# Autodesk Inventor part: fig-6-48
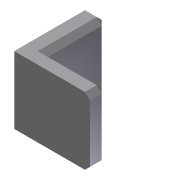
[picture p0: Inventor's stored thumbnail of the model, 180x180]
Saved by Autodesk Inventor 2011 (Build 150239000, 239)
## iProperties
Created: 2009-09
Part Number: fig-6-48
Document SubType Name: Modeling
Designer: Sham
Density: 1 g/cm^3
Author: Sham
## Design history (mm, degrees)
sketch "Sketch1"
  geometry: L1 (1.789, 30)-(1.789, -5); L2 (1.789, -5)-(36.789, -5); L3 (36.789, -5)-(36.789, -15); L4 (36.789, -15)-(-8.211, -15); L5 (-8.211, -15)-(-8.211, 30); L6 (-8.211, 30)-(1.789, 30)
  constraints: 12 end point, 6 perpendicular
  dimensions: "d0" = 10 distance of L5.end L1.start; "d1" = 35 distance of L1.start L1.end; "d2" = 45 distance of L3.end L4.end; "d3" = 10 distance of L2.end L3.end (derived)
extrude "Extrusion1" new body sketch "Sketch1" distance "d4" = 40; taper "d5" = 0 deg
chamfer "Chamfer1" distance "d6" = 3; stored, may be unused: second distance "d7" = 2, angle "d8" = 45 deg
body "Solid1"
other parameters: "d1" = 35
